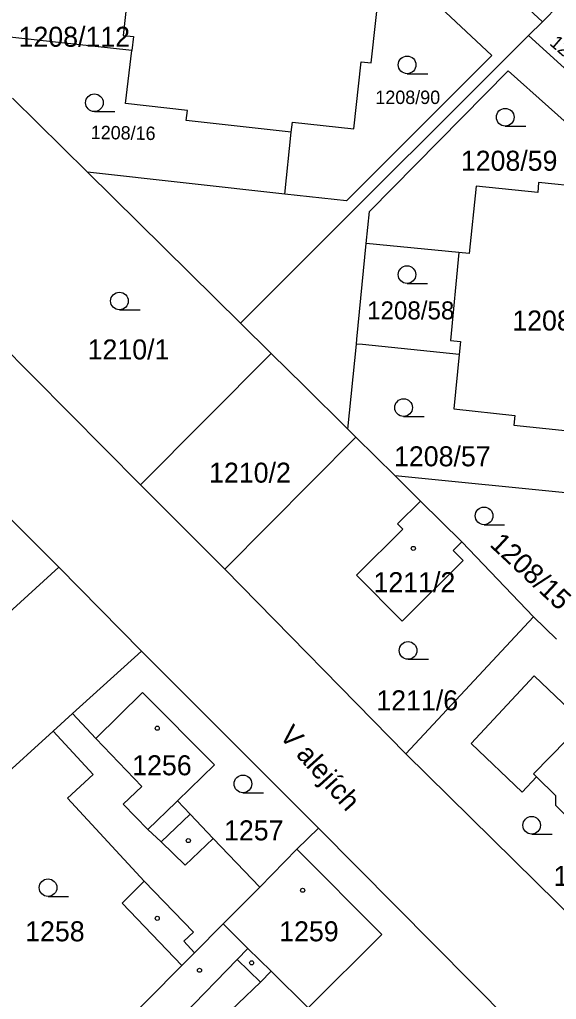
# Model space of a CAD drawing. Extents: x -724107 to -720612, y -1045267 to -1038441.
# Drawn here: x -722081.2 to -722035.6, y -1043824.1 to -1043740.8 of the extents above; entities that cross this region are included whole.
import ezdxf

# ---------------------------------------------------------------- set-up
doc = ezdxf.new("R2010")
doc.units = 0
for name, color, linetype in [('Hranice parcel', 7, 'Continuous'), ('Parcelní čísla', 7, 'Continuous'), ('Pop  PČ popisy', 7, 'Continuous'), ('Vnitřní kresba', 7, 'Continuous'), ('Značky budov', 7, 'Continuous'), ('Značky kultur', 7, 'Continuous')]:
    doc.layers.add(name, color=color, linetype=linetype)

msp = doc.modelspace()

# ---------------------------------------------------------------- linework, layer by layer
at = {"layer": 'Hranice parcel'}
for p, q in [((-722036.78, -1043740.98), (-722062.34, -1043716.94)), ((-722035.37, -1043739.57), (-722036.78, -1043740.98)), ((-722037.95, -1043742.15), (-722036.78, -1043740.98)), ((-722071.7, -1043743.42), (-722084.9, -1043741.97)), ((-722009.8, -1043767.74), (-722037.95, -1043742.15)), ((-722075.45, -1043753.76), (-722081.83, -1043747.47)), ((-722058.68, -1043755.61), (-722058.13, -1043750.36)), ((-722077.91, -1043787.33), (-722114.01, -1043751.13)), ((-722097.4, -1043753.73), (-722070.94, -1043780.32)), ((-722058.68, -1043755.61), (-722075.45, -1043753.76)), ((-722075.45, -1043753.76), (-722062.46, -1043766.58)), ((-722043.88, -1043760.58), (-722051.77, -1043759.8)), ((-722059.83, -1043769.17), (-722062.46, -1043766.58)), ((-722053.32, -1043775.59), (-722052.59, -1043768.36)), ((-722070.94, -1043780.32), (-722059.83, -1043769.17)), ((-722052.64, -1043776.26), (-722053.32, -1043775.59)), ((-722063.79, -1043787.5), (-722052.64, -1043776.26)), ((-722049.31, -1043779.56), (-722052.64, -1043776.26)), ((-722047.15, -1043781.7), (-722049.31, -1043779.56)), ((-722030.78, -1043781.42), (-722049.31, -1043779.56)), ((-722070.94, -1043780.32), (-722063.79, -1043787.5)), ((-722043.64, -1043785.17), (-722047.15, -1043781.7)), ((-722037.54, -1043791.53), (-722043.64, -1043785.17)), ((-722086.08, -1043794.79), (-722077.91, -1043787.33)), ((-722077.91, -1043787.33), (-722070.88, -1043794.45)), ((-722063.79, -1043787.5), (-722048.38, -1043803.18)), ((-722037.54, -1043791.53), (-722048.38, -1043803.18)), ((-722035.57, -1043793.43), (-722037.54, -1043791.53)), ((-722070.88, -1043794.45), (-722076.74, -1043799.77)), ((-722055.81, -1043809.51), (-722070.88, -1043794.45)), ((-722076.74, -1043799.77), (-722078.39, -1043801.27)), ((-722078.39, -1043801.27), (-722092.99, -1043814.54)), ((-722048.38, -1043803.18), (-722032.69, -1043818.66)), ((-722057.66, -1043811.3), (-722055.81, -1043809.51)), ((-722038.89, -1043826.55), (-722055.81, -1043809.51)), ((-722060.82, -1043814.53), (-722057.66, -1043811.3))]:
    msp.add_line(p, q, dxfattribs=at)
for points in [[(-722071.61, -1043734.69), (-722072.44, -1043742.15), (-722071.56, -1043742.23), (-722071.7, -1043743.42)], [(-722050.52, -1043736.97), (-722048.09, -1043737.27), (-722041.08, -1043743.85), (-722053.45, -1043756.18), (-722058.68, -1043755.61)], [(-722058.13, -1043750.36), (-722058.02, -1043749.49), (-722052.81, -1043750.07), (-722052.18, -1043744.38), (-722051.33, -1043744.46), (-722050.52, -1043736.97)], [(-722062.46, -1043766.58), (-722058.21, -1043762.34), (-722037.95, -1043742.15)], [(-722058.13, -1043750.36), (-722067.07, -1043749.37), (-722066.97, -1043748.52), (-722072.22, -1043747.92), (-722071.7, -1043743.42)], [(-722051.77, -1043759.8), (-722051.49, -1043757.09), (-722039.7, -1043745.13), (-722032.84, -1043751.26), (-722033.22, -1043755.02)], [(-722033.22, -1043755.02), (-722037.12, -1043754.62), (-722037.18, -1043755.48), (-722042.41, -1043754.94), (-722043.01, -1043760.66), (-722043.88, -1043760.58)], [(-722052.59, -1043768.36), (-722052.55, -1043767.94), (-722051.77, -1043759.8)], [(-722043.88, -1043760.58), (-722044.6, -1043768.05), (-722043.74, -1043768.15), (-722043.85, -1043769.25)], [(-722043.85, -1043769.25), (-722052.07, -1043768.41), (-722052.59, -1043768.36)], [(-722053.32, -1043775.59), (-722057.04, -1043771.92), (-722059.83, -1043769.17)], [(-722043.85, -1043769.25), (-722044.32, -1043773.87), (-722039.12, -1043774.42), (-722039.2, -1043775.25), (-722030.23, -1043776.18)], [(-722047.15, -1043781.7), (-722049.1, -1043783.64), (-722048.65, -1043784.09), (-722052.58, -1043788.01), (-722048.69, -1043791.91), (-722043.53, -1043786.76), (-722044.38, -1043785.91), (-722043.64, -1043785.17)], [(-722035.65, -1043807.57), (-722035.65, -1043806.76), (-722037.27, -1043805.15), (-722038.5, -1043806.44), (-722042.84, -1043802.3), (-722037.48, -1043796.57), (-722033.28, -1043800.56), (-722027.56, -1043806), (-722031.81, -1043810.53), (-722033.72, -1043808.67), (-722034.51, -1043808.72), (-722035.65, -1043807.57)], [(-722060.82, -1043814.53), (-722064.77, -1043810.38), (-722066.73, -1043808.32), (-722067.82, -1043807.18), (-722064.65, -1043804.12), (-722070.78, -1043797.97), (-722074.74, -1043801.87), (-722076.74, -1043799.77)], [(-722078.39, -1043801.27), (-722074.99, -1043804.95), (-722077.16, -1043806.95), (-722070.64, -1043814.01), (-722072.52, -1043815.88), (-722067.45, -1043821.17)], [(-722074.05, -1043835.27), (-722060.76, -1043822.6), (-722059.84, -1043821.67), (-722056.69, -1043824.78), (-722050.43, -1043818.53), (-722057.66, -1043811.3)], [(-722067.45, -1043821.17), (-722066.37, -1043820.09), (-722063.92, -1043817.64), (-722060.92, -1043814.63), (-722060.82, -1043814.53)], [(-722077.63, -1043831.33), (-722070.34, -1043824.1), (-722067.45, -1043821.17)]]:
    msp.add_lwpolyline(points, dxfattribs=at)
at = {"layer": 'Vnitřní kresba'}
for p, q in [((-722074.74, -1043801.87), (-722070.85, -1043805.96)), ((-722070.85, -1043805.96), (-722072.42, -1043807.45)), ((-722070.33, -1043809.61), (-722072.42, -1043807.45)), ((-722070.33, -1043809.61), (-722067.92, -1043807.28)), ((-722067.92, -1043807.28), (-722067.82, -1043807.18)), ((-722066.73, -1043808.32), (-722069.19, -1043810.66)), ((-722070.33, -1043809.61), (-722069.19, -1043810.66)), ((-722067.15, -1043812.64), (-722069.19, -1043810.66)), ((-722064.77, -1043810.38), (-722067.15, -1043812.64)), ((-722070.64, -1043814.01), (-722066.45, -1043818.34)), ((-722063.92, -1043817.64), (-722061.82, -1043819.72)), ((-722066.45, -1043818.34), (-722067.28, -1043819.11)), ((-722067.28, -1043819.11), (-722066.37, -1043820.09)), ((-722061.82, -1043819.72), (-722062.73, -1043820.66)), ((-722061.82, -1043819.72), (-722059.84, -1043821.67)), ((-722067.29, -1043825.38), (-722062.73, -1043820.66)), ((-722062.73, -1043820.66), (-722060.76, -1043822.6))]:
    msp.add_line(p, q, dxfattribs=at)
msp.add_lwpolyline([(-722037.27, -1043805.15), (-722037.53, -1043804.88), (-722033.28, -1043800.56)], dxfattribs=at)
at = {"layer": 'Značky budov'}
for centre in [(-722047.757, -1043785.729), (-722069.527, -1043801.009), (-722066.887, -1043810.559), (-722057.167, -1043814.779), (-722069.527, -1043817.169), (-722061.507, -1043820.949), (-722065.937, -1043821.579)]:
    msp.add_circle(centre, 0.175, dxfattribs=at)
at = {"layer": 'Značky kultur'}
for p, q in [((-722048.283, -1043745.38), (-722046.533, -1043745.38)), ((-722074.873, -1043748.6), (-722073.123, -1043748.6)), ((-722039.943, -1043749.83), (-722038.193, -1043749.83)), ((-722048.293, -1043763.21), (-722046.543, -1043763.21)), ((-722072.743, -1043765.45), (-722070.993, -1043765.45)), ((-722048.583, -1043774.51), (-722046.833, -1043774.51)), ((-722041.743, -1043783.71), (-722039.993, -1043783.71)), ((-722048.203, -1043795.15), (-722046.453, -1043795.15)), ((-722062.243, -1043806.49), (-722060.493, -1043806.49)), ((-722037.693, -1043810.01), (-722035.943, -1043810.01)), ((-722078.813, -1043815.31), (-722077.063, -1043815.31))]:
    msp.add_line(p, q, dxfattribs=at)
for centre in [(-722048.283, -1043744.63), (-722074.873, -1043747.85), (-722039.943, -1043749.08), (-722048.293, -1043762.46), (-722072.743, -1043764.7), (-722048.583, -1043773.76), (-722041.743, -1043782.96), (-722048.203, -1043794.4), (-722062.243, -1043805.74), (-722037.693, -1043809.26), (-722078.813, -1043814.56)]:
    msp.add_circle(centre, 0.75, dxfattribs=at)

# ---------------------------------------------------------------- texts
at = {"layer": 'Parcelní čísla'}
for s, height, p in [('1208/112', 1.7, (-722081.32, -1043743.093)), ('1208/90', 1.139, (-722050.98, -1043747.959)), ('1208/59', 1.7, (-722043.718, -1043753.63)), ('1208/58', 1.534, (-722051.683, -1043766.267)), ('1208/48', 1.7, (-722039.34, -1043767.21)), ('1210/1', 1.7, (-722075.45, -1043769.67)), ('1208/57', 1.7, (-722049.398, -1043778.75)), ('1210/2', 1.7, (-722065.12, -1043780.14)), ('1211/2', 1.7, (-722051.14, -1043789.45)), ('1211/6', 1.7, (-722050.9, -1043799.49)), ('1256', 1.7, (-722071.66, -1043805.01)), ('1257', 1.7, (-722063.85, -1043810.54)), ('1211/3', 1.7, (-722035.83, -1043814.41)), ('1258', 1.7, (-722080.76, -1043819.12)), ('1259', 1.7, (-722059.16, -1043819.12))]:
    msp.add_text(s, height=height, dxfattribs=at).set_placement(p)
for s, height, rotation, p in [('1208/77', 1.139, 319, (-722036.234, -1043742.882)), ('1208/16', 1.139, 359, (-722075.189, -1043750.929)), ('1208/15', 1.7, 317, (-722041.339, -1043785.481))]:
    msp.add_text(s, height=height, rotation=rotation, dxfattribs=at).set_placement(p)
at = {"layer": 'Pop  PČ popisy'}
msp.add_text('V alejích', height=1.7, rotation=312, dxfattribs=at).set_placement((-722059.231, -1043801.698))

doc.saveas('drawing.dxf')
